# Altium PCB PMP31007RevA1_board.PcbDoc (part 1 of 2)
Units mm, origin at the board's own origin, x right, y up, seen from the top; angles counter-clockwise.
Board outline 45.72 x 49.53 mm, 2 copper layers (Top Layer, Bottom Layer), stack 1.575 mm thick; 68 components, 31 nets, 155 pads, 66 vias.
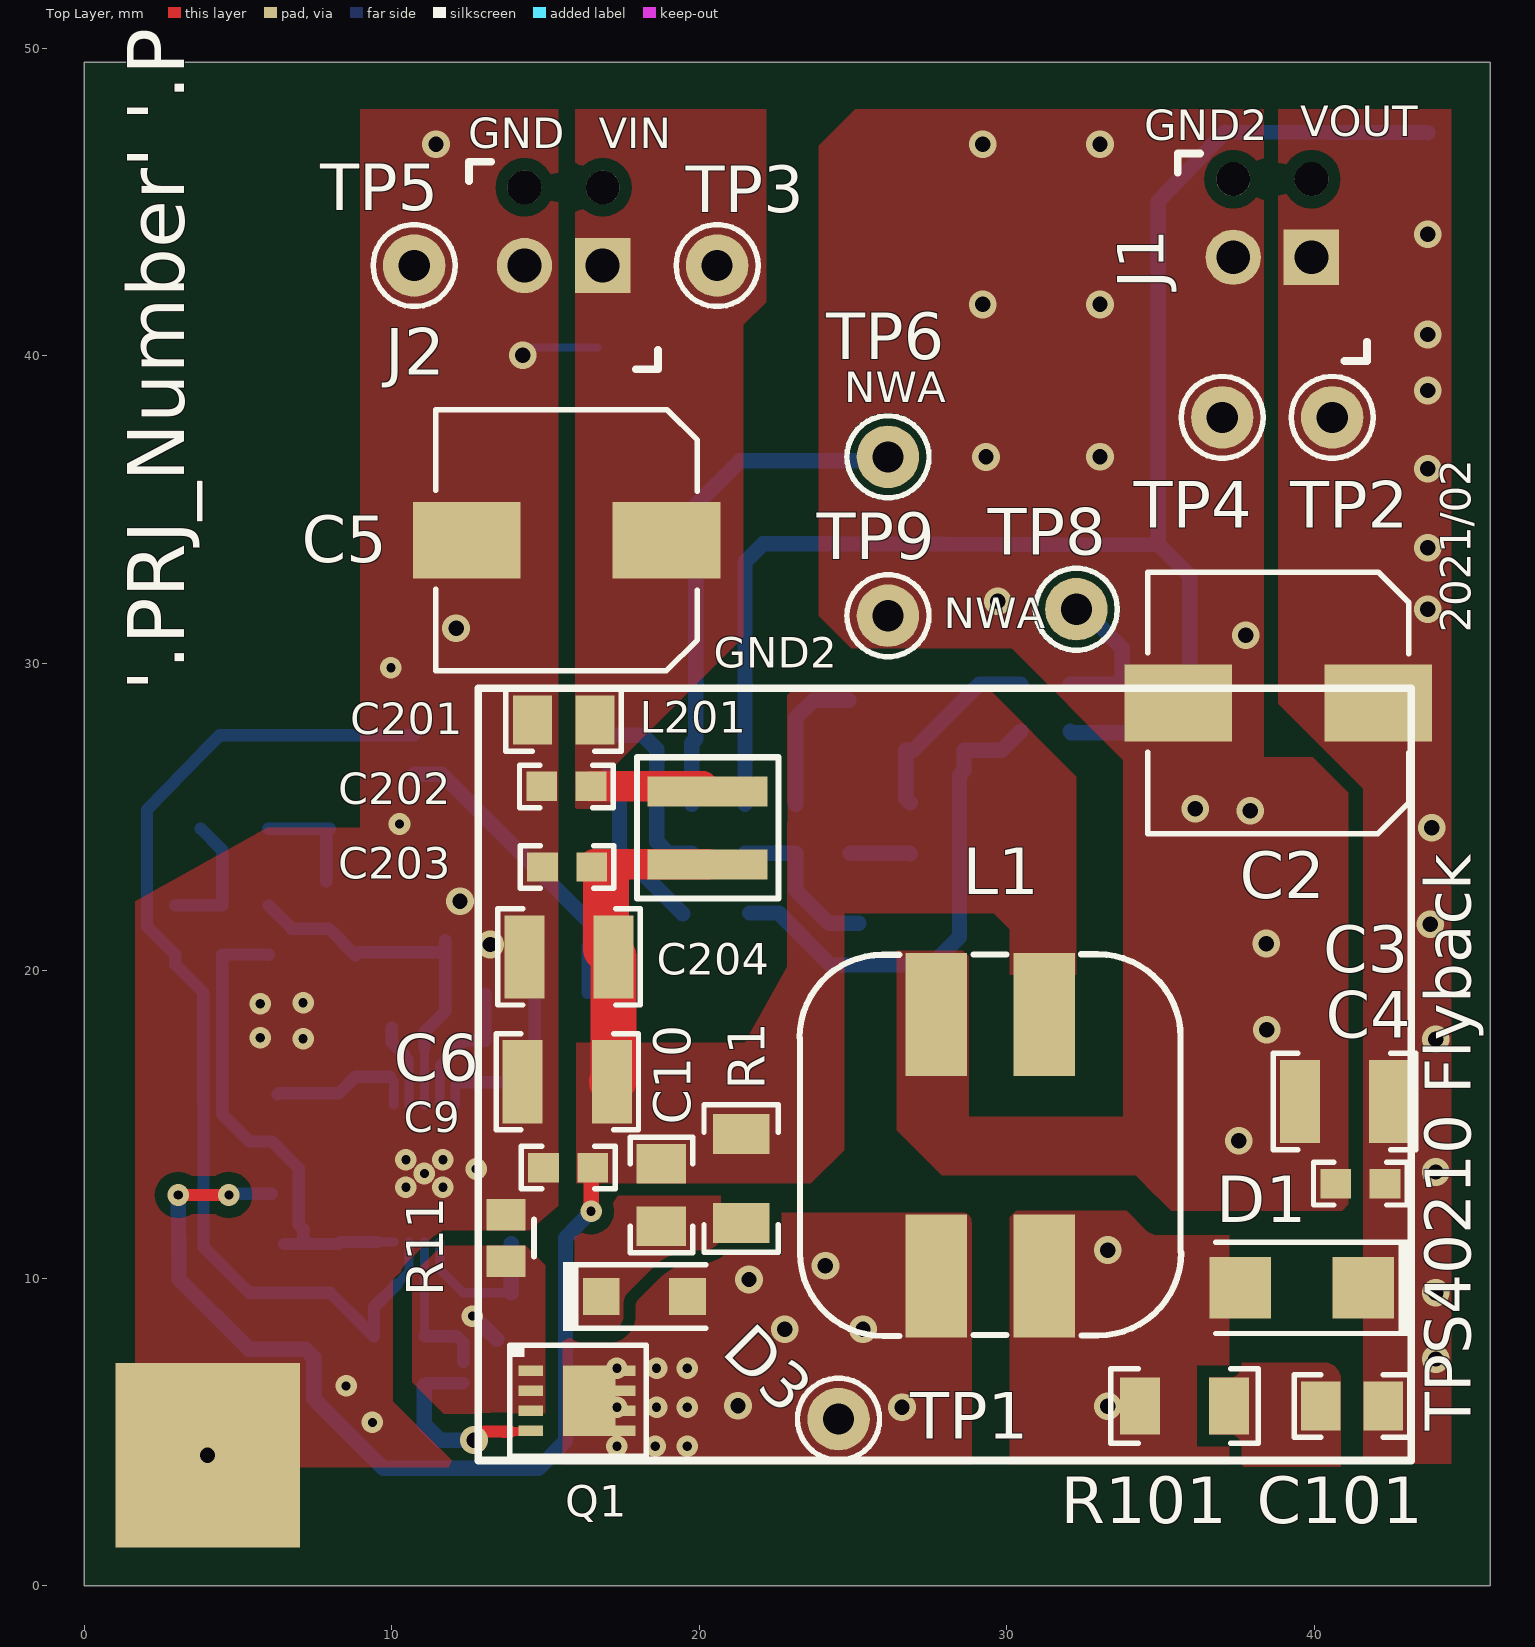
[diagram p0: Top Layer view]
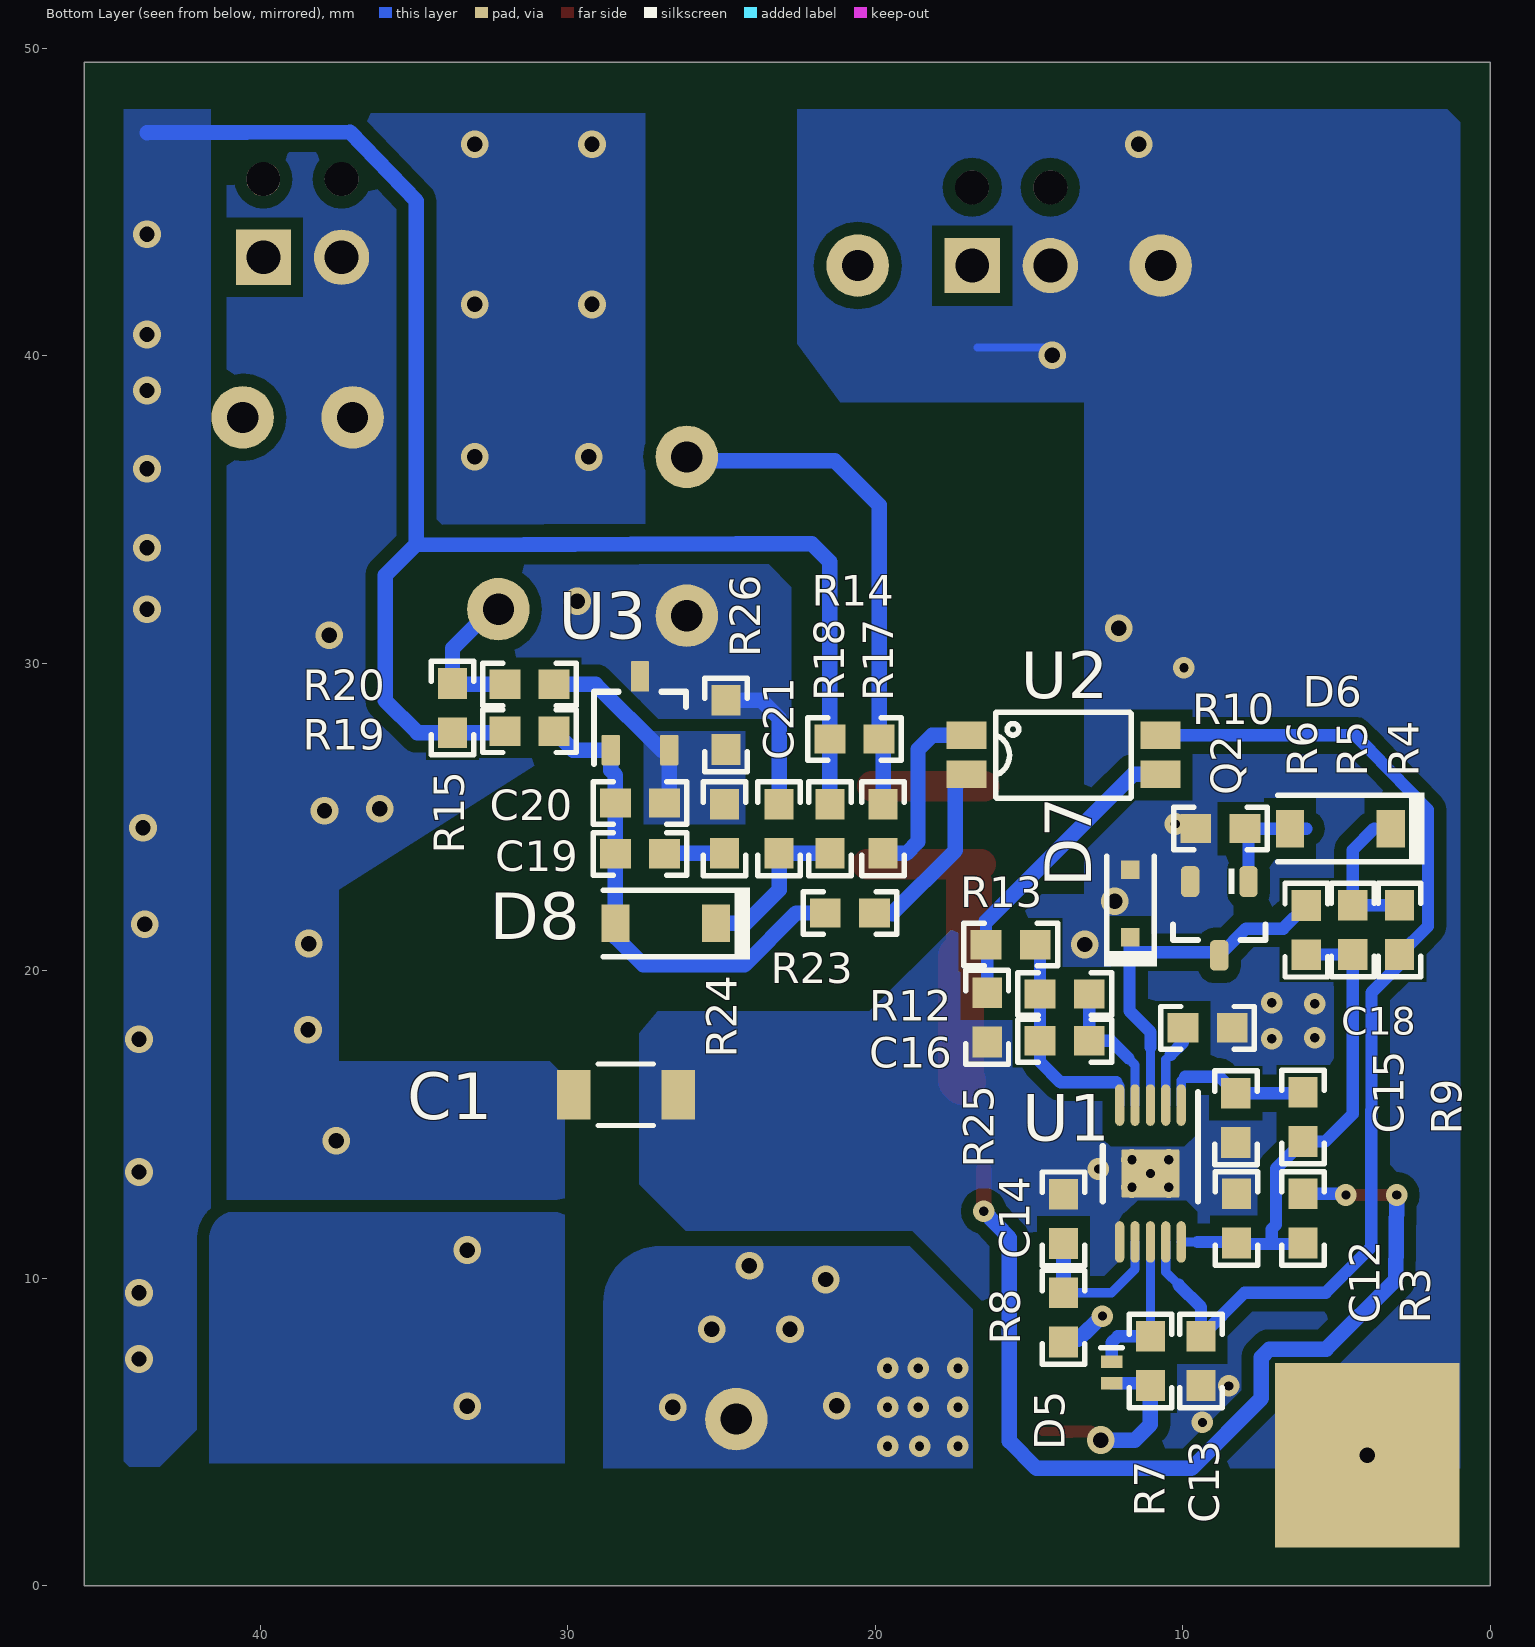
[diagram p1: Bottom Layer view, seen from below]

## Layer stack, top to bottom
Top Solder: solder mask 0.0102, Solder Resist, Dk 3.5
Top Layer: signal copper 0.0356
Dielectric1: core 1.5037, FR-4, Dk 4.8
Bottom Layer: signal copper 0.0356
Bottom Solder: solder mask 0.0102, Solder Resist, Dk 3.5

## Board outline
0,0 0,49.53 45.72,49.53 45.72,0

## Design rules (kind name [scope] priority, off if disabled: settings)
AcuteAngle [All] p1: minimum=4.50000000000000E+0001 checktracksonly=FALSE
AssemblyTestPointUsage [All] p1: valid=2
BoardOutlineClearance BoardOutlineClearance_MountingHoles [OnCopper and InComponentClass('Mounting Holes')] p1: gap=1.016 ignorepadtopadclearanceinfootprint=FALSE
BoardOutlineClearance BoardOutlineClearance_Poly [OnCopper and IsPoly] p2: gap=0.635 ignorepadtopadclearanceinfootprint=FALSE
BoardOutlineClearance [OnCopper and Not InComponentClass('Logo') and not InComponentClass('FiducialMark') and not InRegion(1000,500,4000,800) and not InPoly] p3: gap=1.905 ignorepadtopadclearanceinfootprint=FALSE
Clearance Clearance_Keepouts [((IsTrack Or IsArc) And Not InPoly) And IsFree and IsKeepOut vs ((IsTrack Or IsArc) And Not InPoly) And IsFree and IsKeepOut] p1: gap=0 ignorepadtopadclearanceinfootprint=FALSE
Clearance Clearance_Poly [InPolygon] p2: gap=0.4 ignorepadtopadclearanceinfootprint=FALSE except(0: Arc-Hole Track-Hole SMDPad-Hole THPad-Hole Via-Hole Fill-Hole Poly-Hole Region-Hole Text-Hole)
Clearance Clearance_FiducialMark [IsKeepOut and InComponentClass('FiducialMark') vs IsPad and InComponentClass('FiducialMark')] p3: gap=0 ignorepadtopadclearanceinfootprint=FALSE
Clearance [All] p4: gap=0.2 ignorepadtopadclearanceinfootprint=FALSE except(0: Arc-Hole Track-Hole SMDPad-Hole THPad-Hole Via-Hole Fill-Hole Poly-Hole Region-Hole Text-Hole)
ComponentClearance ComponentClearance_MountingHoles_FiducialMarks [InComponentClass('Mounting Holes') vs InComponentClass('FiducialMark')] p1: gap=1.27 collisioncheckmode=3 verticalgap=0.254 showdistances=FALSE
ComponentClearance ComponentClearance_Shunt [InComponentClass('Header') vs InComponentClass('Shunt')] p2: gap=0 collisioncheckmode=3 verticalgap=0 showdistances=FALSE
ComponentClearance ComponentClearance_Logo [InComponentClass('Logo')] p3: gap=1.27 collisioncheckmode=3 verticalgap=0.254 showdistances=FALSE
ComponentClearance ComponentClearance_ScrewToNut [(HasFootprint('NY PMS 440 0025 PH')) vs (HasFootprint('Keystone_1902C'))] p4: gap=0.127 collisioncheckmode=3 verticalgap=0.254 showdistances=FALSE
ComponentClearance ComponentClearance_MountingHoles [InComponentClass('Mounting Holes')] p5: gap=6.35 collisioncheckmode=3 verticalgap=2540 showdistances=FALSE
ComponentClearance ComponentClearance_SmallPassives [HasFootprint('0201*') or HasFootprint('0402*') or HasFootprint('0508') or HasFootprint('0603*') or HasFootprint('0612') or HasFootprint('0805*') or HasFootprint('0815*') or HasFootprint('0830*') or HasFootprint('1206*') or HasFootprint('1210*') or HasFootprint('1808*') or HasFootprint('1812*') or HasFootprint('1825*') or HasFootprint('2010*') or HasFootprint('2220*') or HasFootprint('2225*') or HasFootprint('2512*') or HasFootprint('2728*') or HasFootprint('3518*') or HasFootprint ('X1-DFN1006-2') vs HasFootprint('0201*') or HasFootprint('0402*') or HasFootprint('0508') or HasFootprint('0603*') or HasFootprint('0612') or HasFootprint('0805*') or HasFootprint('0815*') or HasFootprint('0830*') or HasFootprint('1206*') or HasFootprint('1210*') or HasFootprint('1808*') or HasFootprint('1812*') or HasFootprint('1825*') or HasFootprint('2010*') or HasFootprint('2220*') or HasFootprint('2225*') or HasFootprint('2512*') or HasFootprint('2728*') or HasFootprint('3518*') or HasFootprint ('X1-DFN1006-2')] p6: gap=0.38 collisioncheckmode=3 verticalgap=0.254 showdistances=FALSE
ComponentClearance ComponentClearance_THtoSMT [IsThruComponent vs IsSMTComponent] p7: gap=1.016 collisioncheckmode=3 verticalgap=0.762 showdistances=FALSE
ComponentClearance ComponentClearance_THtoTH [IsThruComponent vs IsThruComponent] p8: gap=0.762 collisioncheckmode=3 verticalgap=0.762 showdistances=FALSE
ComponentClearance [All] p9: gap=0.762 collisioncheckmode=3 verticalgap=0.254 showdistances=FALSE
DiffPairsRouting [All] p1: maxlimit=2.54 minlimit=0.254 mostfreqgap=0.254 toplayer_minwidth=0.381 toplayer_maxwidth=0.381 toplayer_prefwidth=0.381 bottomlayer_minwidth=0.381 bottomlayer_maxwidth=0.381 bottomlayer_prefwidth=0.381 maxuncoupledlength=25.4
FabricationTestPointUsage TestPointUsage [All] p1: valid=2 allowmultiple=FALSE
FabricationTestpoint Testpoint [All] p1: side=3 testpointundercomponent=TRUE minsize=1.016 maxsize=2.54 preferedsize=1.524 minholesize=0 maxholesize=1.016 preferedholesize=0.813 testpointgrid=0.025 allowsidetop=TRUE allowsidebottom=TRUE usegrid=TRUE gridtolerance=0
FanoutControl Fanout_LCC [IsLCC] p1: bgadir=Out bgaviamode=Centered fanoutstyle=Auto fanoutdirection=Alternating viagrid=0.025 // Fanout_LCC (Default Rule)
FanoutControl Fanout_BGA [IsBGA] p2: bgadir=Out bgaviamode=Centered fanoutstyle=Auto fanoutdirection=Alternating viagrid=0.025 // Fanout_BGA (Default Rule)
FanoutControl Fanout_Default [All] p4: bgadir=Out bgaviamode=Centered fanoutstyle=Auto fanoutdirection=Alternating viagrid=0.025 // Fanout_Default (Default Rule)
FanoutControl Fanout_Small [(CompPinCount < 5)] p5: bgadir=Out bgaviamode=Centered fanoutstyle=Auto fanoutdirection=OutThenIn viagrid=0.025 // Fanout_Small (Default Rule)
HoleSize [All] p1: absolutevalues=TRUE maxlimit=6.375 minlimit=0.3 maxpercent=80.000 minpercent=20.000
MinimumAnnularRing MinimumAnnularRing_ThermalPadVias [IsVia and InAnyComponent] p1: minimumring=0.15
MinimumAnnularRing [All] p2: minimumring=0.2
MinimumSolderMaskSliver MinimumSolderMaskSliver_Logo [InComponentClass('Logo') vs InComponentClass('Logo')] p1: minsoldermaskwidth=0.018
MinimumSolderMaskSliver [All] p2: minsoldermaskwidth=0.1
PlaneConnect [All] p1: planeconnectstyle=Relief reliefexpansion=0.254 reliefentries=4 reliefconductorwidth=0.254 reliefairgap=0.254
PolygonConnect [All] p1: connectstyle=Direct reliefconductorwidth=0.254 reliefentries=4 polygonreliefangle="90 Angle" airgapwidth=0.254
RoutingVias ThermalPadVias [IsVia and InAnyComponent] p1: holewidth=0.3 width=0.7 viastyle="Through Hole" minholewidth=0.3 minwidth=0.6 maxholewidth=0.6 maxwidth=1.6
RoutingVias [All] p2: holewidth=0.3 width=0.7 viastyle="Through Hole" minholewidth=0.3 minwidth=0.6 maxholewidth=1.016 maxwidth=2
SilkToBoardRegionClearance [Not ((IsComment or IsDesignator) And (Hide <> 'False')) and not InRegion(1000,500,4000,800)] p1:
SilkToSilkClearance SilkToSilkClearance_Pb-FreeLogo [(HasFootprint('Pb-Free_Overlay_Medium') OR HasFootprint('Pb-Free_Overlay_Small')) vs (HasFootprint('Pb-Free_Overlay_Medium') OR HasFootprint('Pb-Free_Overlay_Small'))] p1: silktosilkclearance=0
SilkToSilkClearance [All] p2: silktosilkclearance=0.102
SilkToSolderMaskClearance SilkToComponentPadClearance [(IsPad or IsFill or IsRegion) and InAnycomponent] p1: minsilkscreentomaskgap=0.127 clearancetoexposedcopper=TRUE
SilkToSolderMaskClearance "Silk to Solder Mask Opening" [All] p2: minsilkscreentomaskgap=0.102 clearancetoexposedcopper=FALSE
SolderMaskExpansion [All] p1: expansion=0.05 istentingtop=FALSE
Width [All] p1: maxlimit=2.54 minlimit=0.152 preferedwidth=0.254 checkconnectedcopper=TRUE
15 further rules are at their usual default settings.

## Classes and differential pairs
net class L201_Nets: NetC6_1 VIN
net class C204_Nets: GND NetC6_1
net class C203_Nets: GND NetC6_1
net class C202_Nets: GND VIN
net class C201_Nets: GND VIN
net class U3_Nets: GND2 NetC19_2 NetC20_2
net class U2_Nets: NetR13_1 NetR17_1 NetR23_2 VBP
net class U1_Nets: GND NetC12_1 NetC14_1 NetC15_1 NetC16_1 NetC16_2 NetC18_1 NetD5_1 NetD7_1 VBP
net class TP9_Nets: GND2
net class TP8_Nets: NetR15_2
net class TP6_Nets: NetR14_1
net class TP5_Nets: GND
net class TP4_Nets: GND2
net class TP3_Nets: VIN
net class TP2_Nets: VOUT
net class TP1_Nets: NetD3_2
net class R101_Nets: NetC101_2 NetD1_2
net class R26_Nets: GND2 NetC20_2
net class R25_Nets: GND NetR13_1
net class R24_Nets: NetC19_1 NetC20_2
net class R23_Nets: NetC19_2 NetR23_2
net class R20_Nets: NetC20_2 NetR15_2
net class R19_Nets: NetC19_2 VOUT
net class R18_Nets: NetC21_1 VOUT
net class R17_Nets: NetR14_1 NetR17_1
net class R15_Nets: NetR15_2 VOUT
net class R14_Nets: NetR14_1 VOUT
net class R13_Nets: NetC16_2 NetR13_1
net class R12_Nets: NetC16_1 NetC16_2
net class R11_Nets: GND NetQ1_1
net class R10_Nets: GND NetD6_2
net class R9_Nets: NetC12_1 NetC15_1
net class R8_Nets: NetC14_1 NetQ1_1
net class R7_Nets: NetD5_1 NetD5_2
net class R6_Nets: NetC12_1 NetD7_1
net class R5_Nets: NetC12_1 NetD6_1
net class R4_Nets: NetD6_1 VBP
net class R3_Nets: NetC6_1 NetC12_1
net class R1_Nets: NetC6_1 NetC10_2
net class Q2_Nets: GND NetD6_2 NetD7_1
net class Q1_Nets: NetD3_2 NetD5_2 NetQ1_1
net class L1_Nets: GND2 NetC6_1 NetD1_2 NetD3_2
net class J2_Nets: GND VIN
net class J1_Nets: GND2 VOUT
net class D8_Nets: NetC19_2 NetC21_1
net class D7_Nets: GND NetD7_1
net class D6_Nets: NetD6_1 NetD6_2
net class D5_Nets: NetD5_1 NetD5_2
net class D3_Nets: NetC10_2 NetD3_2
net class D1_Nets: NetD1_2 VOUT
net class C101_Nets: NetC101_2 VOUT
net class C21_Nets: GND2 NetC21_1
net class C20_Nets: NetC19_2 NetC20_2
net class C19_Nets: NetC19_1 NetC19_2
net class C18_Nets: GND NetC18_1
net class C16_Nets: NetC16_1 NetC16_2
net class C15_Nets: GND NetC15_1
net class C14_Nets: GND NetC14_1
net class C13_Nets: GND VBP
net class C12_Nets: GND NetC12_1
net class C10_Nets: NetC6_1 NetC10_2
net class C9_Nets: GND NetC6_1
net class C6_Nets: GND NetC6_1
net class C5_Nets: GND VIN
net class C4_Nets: GND2 VOUT
net class C3_Nets: GND2 VOUT
net class C2_Nets: GND2 VOUT
net class C1_Nets: GND GND2

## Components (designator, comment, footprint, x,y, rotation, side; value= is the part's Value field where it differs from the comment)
C1 "C1206C102KGRACAUTO" 1206_180 28.111,15.958 r180 bottom value=1000pF
C2 "EEHZA1H680P" SM_RADIAL_8MM 38.821,28.702 r180 top value=68uF
C3 "GRM32ER71H106KA12L" 1210_270 40.975,15.735 r180 top value=10uF
C4 "GCM188R71H104KA57D" 0603 41.491,13.068 r180 top value=0.1uF
C5 "EEHZA1H680P" SM_RADIAL_8MM 15.678,33.992 r180 top value=68uF
C6 "GRM32ER71H106KA12L" 1210_270 15.701,16.383 r180 top value=10uF
C9 "GCM188R71H104KA57D" 0603 15.731,13.589 r180 top value=0.1uF
C10 "GRM21BR72A103MA01L" 0805_HV 18.759,12.7 r270 top value=0.01uF
C12 "UMK107AB7105KA-T" 0603 8.254,11.938 r90 bottom value=1uF
C13 "GRM188R71C105KA12D" 0603 9.413,7.303 r270 bottom value=1uF
C14 "GRM188R71H221KA01D" 0603 13.884,11.924 r90 bottom value=220pF
C15 "GRM1885C1H471JA01D" 0603 8.278,15.21 r270 bottom value=470pF
C16 "GRM1885C1H101JA01D" 0603 13.844,17.717 r0 bottom value=100pF
C18 "GRM188R71C105KA12D" 0603 9.197,18.138 r180 bottom value=1uF
C19 "GRM188R71E332KA01D" 0603 27.654,23.795 r0 bottom value=3300pF
C20 "GRM1885C1H470JA01D" 0603 27.654,25.446 r180 bottom value=47pF
C21 "GRM188R71C105KA12D" 0603 23.13,24.61 r90 bottom value=1uF
C101 "GRM2165C2A221JA01D" 0805_HV 41.22,5.842 r180 top value=220pF
C201 "GRM21BR71H105KA12L" 0805_HV 15.582,28.15 r180 top value=1uF
C202 "885012206114" 0603 15.671,25.991 r180 top value=0.01uF
C203 "GCM188R71H104KA57D" 0603 15.693,23.368 r180 top value=0.1uF
C204 "GRM32ER71H106KA12L" 1210_270 15.759,20.447 r180 top value=10uF
D1 "B1100-13-F" SMA 39.583,9.682 r180 top value=100V
D3 "BAT46WH,115" SOD-123F 18.206,9.398 r0 top value=100V
D5 "BAT54LP-7" X1-DFN1006-2 12.318,6.932 r270 bottom value=30V
D6 "MMSZ5246B-7-F" SOD-123 4.879,24.615 r0 bottom value=16V
D7 "MMSZ5233BS-7-F" SOD-323 11.705,22.184 r90 bottom value=6V
D8 "MMSD914" SOD-123 26.818,21.533 r0 bottom value=100V
J1 "1725656" CONN_1725656 38.629,43.195 r180 top
J2 "1725656" CONN_1725656 15.579,42.926 r180 top
L1 "MSD1260-223ML" MSD1260 29.46,14.323 r90 top value=22uH
L201 "XEL4030-332MEB" XEL4030_310 20.266,24.638 r270 top value=3.3uH
Q1 "BSZ160N10NS3 G" PG-TSDSON-8 16.057,6.01 r0 top value=100V
Q2 "MMBT2222A" SOT-23 8.816,21.694 r270 bottom value=0.3V
R1 "CRCW120610K0JNEA" 1206 21.357,13.238 r90 top value=10k
R3 "CRCW060310R0FKEA" 0603 6.095,11.938 r90 bottom value=10.0
R4 "CRCW0603249KFKEA" 0603 2.952,21.321 r270 bottom value=249k
R5 "CRCW060320K0FKEA" 0603 4.476,21.321 r270 bottom value=20.0k
R6 "CRCW060320K0FKEA" 0603 5.988,21.313 r270 bottom value=20.0k
R7 "CRCW060310R0FKEA" 0603 11.056,7.303 r90 bottom value=10.0
R8 "CRCW06031K00FKEA" 0603 13.884,8.721 r270 bottom value=1.00k
R9 "CRCW0603200KFKEA" 0603 6.095,15.24 r270 bottom value=200k
R10 "CRCW0603100KFKEA" 0603 8.778,24.615 r180 bottom value=100k
R11 "WSLP0805R0300FEB" WSLP0805 13.715,11.303 r270 top value=0.03
R12 "CRCW060320K0FKEA" 0603 13.844,19.241 r180 bottom value=20.0k
R13 "CRCW06034K99FKEA" 0603 15.6,20.841 r180 bottom value=4.99k
R14 "CRCW060349R9FKEA" 0603 20.679,27.531 r0 bottom value=49.9
R15 "CRCW060349R9FKEA" 0603 33.75,28.536 r90 bottom value=49.9
R17 "CRCW06034K99FKEA" 0603 19.748,24.61 r90 bottom value=4.99k
R18 "CRCW060349K9FKEA" 0603 21.479,24.61 r90 bottom value=49.9k
R19 "CRCW060320K0FKEA" 0603 31.248,27.783 r0 bottom value=20.0k
R20 "CRCW060349K9FKEA" 0603 31.248,29.307 r0 bottom value=49.9k
R23 "CRCW06030000Z0EA" 0603 20.828,21.871 r180 bottom value=0
R24 "CRCW0603100KFKEA" 0603 24.902,24.61 r90 bottom value=100k
R25 "CRCW06031K00FKEA" 0603 16.362,18.479 r90 bottom value=1.00k
R26 "CRCW06035K76FKEA" 0603 24.86,27.986 r270 bottom value=5.76k
R101 "CRCW120622R0JNEA" 1206 35.774,5.842 r0 top value=22
TP1 "5002" Keystone5002 24.521,5.412 r0 top
TP2 "5000" Keystone5000 40.577,37.988 r90 top value=Red
TP3 "5000" Keystone5000 20.574,42.926 r90 top value=Red
TP4 "5001" Keystone5001 37,37.988 r90 top value=Black
TP5 "5001" Keystone5001 10.721,42.926 r90 top value=Black
TP6 "5003" Keystone5003 26.13,36.703 r90 top
TP8 "5003" Keystone5003 32.258,31.75 r90 top
TP9 "5001" Keystone5001 26.13,31.54 r90 top value=Black
U1 "TPS40210" DGQ0010D_N 11.056,13.399 r270 bottom
U2 "TCMT1107" SOP-4 13.884,27.013 r180 bottom
U3 "TL431" DBZ0003A_N 27.654,28.367 r90 bottom

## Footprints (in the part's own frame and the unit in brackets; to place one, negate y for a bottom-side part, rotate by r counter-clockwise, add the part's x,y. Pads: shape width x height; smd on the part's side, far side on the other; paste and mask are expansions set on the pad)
0603 [mm] "0603 from SM-752 data"
  rect 1x0.95 smd: 1(-0.8,0) 2(0.8,0)
  silkscreen extent -1.52,-0.69 1.52,0.69, body extent -0.87,-0.47 0.87,0.47, height 1
0805_HV [mil] "0805 with 30mil clearance between pads"
  rect 50x63 smd: 1(-40,0) 2(40,0)
  silkscreen extent -74,-40 74,40, body extent -43,-29 43,29, height 57
1206 [mm] "1206 from SM-752 data"
  rect 1.3x1.85 smd: 1(-1.45,0) 2(1.45,0)
  silkscreen extent -2.4,-1.21 2.4,1.21, body extent -1.7,-0.9 1.7,0.9, height 1.35
1206_180 [mm] "1206_180"
  rect 1.1x1.6 smd: 1(-1.7,0) 2(1.7,0)
  silkscreen extent -0.9,-1 0.9,1, body extent -1.75,-0.95 1.75,0.95, height 1.8
1210_270 [mm] "1210"
  rect 1.3x2.7 smd: 1(-1.45,0) 2(1.45,0)
  silkscreen extent -2.32,-1.57 2.32,1.57, body extent -1.7,-1.35 1.7,1.35, height 2.7
CONN_1725656 [mm] "Phoenix Contact"
  rect 1.8x1.8 hole 1.1: 1(-1.27,0)
  round 1.8 hole 1.1: 2(1.27,0)
  round 1.1 hole 1.1 unplated: MH1(-1.275,-2.54) MH2(1.27,-2.54)
  silkscreen extent -3.08,-3.37 3.08,3.37, body extent -2.77,-3.1 2.77,3.1, height 8.52
DBZ0003A_N [mm] "SOT23, 3-Leads, Body 2.9x1.3mm, Pitch 0.95mm, Lead Span 2.4mm, IPC Medium Density"
  rrect17% 1x0.6 smd: 1(-1.2,0.95) 2(-1.2,-0.95) 3(1.2,0)
  silkscreen extent -1.65,-1.5 0.7,1.5, body extent -1.26,-1.46 1.26,1.46, height 0.98
DGQ0010D_N [mm] "TSSOP, 10-Leads, Body 3x3mm, Pitch 0.5mm, Thermal Pad 1.88x1.57mm, IPC Medium Density"
  rrect100% 1.35x0.3 smd: 1(-2.225,1) 2(-2.225,0.5) 3(-2.225,0) 4(-2.225,-0.5) 5(-2.225,-1) 6(2.225,-1) 7(2.225,-0.5) 8(2.225,0) 9(2.225,0.5) 10(2.225,1)
  rrect6% 1.57x1.88 smd: 11(0,0)
  silkscreen extent -2.65,-1.55 0.9,1.55, body extent -2.46,-1.5 2.46,1.5, height 1.1
Keystone5000 [mil] "For Keystone 500x miniature loop terminals"
  round 80 hole 40: 1(0,0)
  silkscreen extent -52,-52 52,52, body extent -49,-49 49,49, height 182
Keystone5001 [mil] "For Keystone 500x miniature loop terminals"
  round 80 hole 40: 1(0,0)
  silkscreen extent -52,-52 52,52, body extent -49,-49 49,49, height 182
Keystone5002 [mil] "For Keystone 500x miniature loop terminals"
  round 80 hole 40: 1(0,0)
  silkscreen extent -52,-52 52,52, body extent -49,-49 49,49, height 182
Keystone5003 [mil] "For Keystone 500x miniature loop terminals"
  round 80 hole 40: 1(0,0)
  silkscreen extent -52,-52 52,52, body extent -49,-49 49,49, height 182
MSD1260 [mm] "COILCRAFT"
  rect 4x2 smd mask+0.051: 1(-4.25,1.753) 2(-4.25,-1.753) 3(4.25,-1.753) 4(4.25,1.753)
  silkscreen extent -6.21,-6.21 6.21,6.21, body extent -6.1,-6.1 6.1,6.1, height 6
PG-TSDSON-8 [mm] "Infineon recommended land pattern"
  rect 0.8x0.34 smd: 1(-1.538,0.975) 2(-1.538,0.325) 3(-1.538,-0.325) 4(-1.538,-0.975)
  rect 0.65x0.34 smd: 5(1.538,-0.975) 6(1.538,-0.325) 7(1.538,0.325) 8(1.538,0.975)
  rect 1.71x2.29 smd: 9(0.358,0)
  silkscreen extent -2.22,-1.8 2.22,1.8, body extent -1.7,-1.7 1.7,1.7, height 1.1
SM_RADIAL_8MM [mm] "Nichicon 8x10"
  rect 3.5x2.5 smd: 1(-3.25,0) 2(3.25,0)
  silkscreen extent -4.25,-4.25 4.25,4.25, body extent -4.25,-4.25 4.25,4.25, height 10.5
SMA [mm] "Molded Diode, 2-Leads, Body 4.3x2.6mm, IPC Medium Density, based on OnSemi component dimensions and land pattern"
  rect 2x2 smd: 1(-2,0) 2(2,0)
  silkscreen extent -3.66,-1.57 2.79,1.57, body extent -2.6,-1.3 2.6,1.3, height 2.42
SOD-123 [mm] "On Semi recommended land pattern"
  rect 0.915x1.22 smd: 1(-1.637,0) 2(1.637,0)
  silkscreen extent -2.74,-1.17 2.03,1.17, body extent -1.93,-0.9 1.93,0.9, height 1.35
SOD-123F [mm] "NXP recommended land pattern"
  rect 1.2x1.2 smd paste-0.05: 1(-1.4,0) 2(1.4,0)
  silkscreen extent -2.64,-1.12 2.01,1.12, body extent -1.8,-0.85 1.8,0.85, height 1.2
SOD-323 [mm] "NXP recommended land pattern"
  rect 0.6x0.6 smd paste-0.05: 1(-1.1,0) 2(1.1,0)
  silkscreen extent -2.06,-0.86 1.53,0.86, body extent -1.3,-0.67 1.3,0.68, height 1.1
SOP-4 [mm] "Vishay Half Pitch Mini-Flat Package"
  rect 1.3x0.9 smd: 1(-3.15,0.635) 2(-3.15,-0.635) 3(3.15,-0.635) 4(3.15,0.635)
  silkscreen extent -2.2,-1.41 2.2,1.39, body extent -3.5,-1.4 3.5,1.4, height 2.12
SOT-23 [mm] "SOT23, 3-Leads, Body 2.9x1.3mm, Pitch 0.95mm, Lead Span 2.5mm, IPC Medium Density"
  rrect50% 1x0.6 smd: 1(-1.2,0.95) 2(-1.2,-0.95) 3(1.2,0)
  silkscreen extent -1.63,-1.5 0.7,1.5, body extent -1.16,-1.45 1.21,1.45, height 1
WSLP0805 [mm] "Vishay"
  rect 1.02x1.27 smd: 1(-0.76,0) 2(0.76,0)
  silkscreen extent -0.6,-0.9 0.6,0.9, body extent -1.14,-0.76 1.14,0.76, height 0.64
X1-DFN1006-2 [mm] "DIODES, INC"
  rect 0.4x0.7 smd: 1(-0.35,0) 2(0.35,0)
  silkscreen extent -0.8,-0.35 -0.8,0.35, body extent -0.54,-0.34 0.54,0.34, height 0.53
XEL4030_310 [mm] "SMD, 2-Leads, Body 4x4mm, Pitch 2.37mm"
  rect 0.98x3.9 smd: 1(-1.185,0) 2(1.185,0)
  silkscreen extent -2.3,-2.3 2.3,2.3, body extent -2.15,-2.15 2.15,2.15, height 3.1

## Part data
C1: "CAP, CERM, 1000 pF, 2000 V,+/- 10%, X7R, AEC-Q200 Grade 1, 1206", Cap_Case=1206, Manufacturer=Kemet, Supplier Part Number 1=399-12976-1-ND, TempCo=X7R, Tolerance_%=10, Value2=2000V, ValueDisplayed=1000pF
C2 C5: "CAP, Polymer Hybrid, 68 µF, 50 V,+/- 20%, 30 ohm, 8x10 SMD", Manufacturer=Panasonic, Supplier Part Number 1=P15445CT-ND, Tolerance_%=20, Value1="30 ohm", Value2=50V, ValueDisplayed=68µF
C3 C6 C204: "CAP, CERM, 10 µF, 50 V,+/- 10%, X7R, 1210", Cap_Case=1210, Manufacturer=MuRata, Supplier Part Number 1=490-6544-1-ND, TempCo=X7R, Tolerance_%=10, Value1=Unknown, Value2=50V, ValueDisplayed=10µF
C4 C9 C203: "CAP, CERM, 0.1 µF, 50 V, +/- 10%, X7R, 0603", Cap_Case=0603, Manufacturer=MuRata, Supplier Part Number 1=490-4779-1-ND, TempCo=X7R, Tolerance_%=10, Value1="0.02 ohm", Value2=50V, ValueDisplayed=0.1µF
C10: "CAP, CERM, 0.01 µF, 100 V, +/- 20%, X7R, 0805", Cap_Case=0805, Manufacturer=MuRata, Supplier Part Number 1=490-1653-1-ND, TempCo=X7R, Tolerance_%=20, Value1=Unknown, Value2=100V, ValueDisplayed=0.01µF
C12: "CAP, CERM, 1 µF, 50 V,+/- 10%, X7R, 0603", Cap_Case=0603, Manufacturer="Taiyo Yuden", Supplier Part Number 1=587-3247-1-ND, TempCo=X7R, Tolerance_%=10, Value2=50V, ValueDisplayed=1µF
C13 C21: "CAP, CERM, 1 µF, 16 V, +/- 10%, X7R, 0603", Cap_Case=0603, Manufacturer=MuRata, Supplier Part Number 1=490-3900-1-ND, TempCo=X7R, Tolerance_%=10, Value1="0.011 ohm", Value2=16V, ValueDisplayed=1µF
C14: "CAP, CERM, 220 pF, 50 V,+/- 10%, X7R, 0603", Cap_Case=0603, Manufacturer=MuRata, Supplier Part Number 1=490-1483-1-ND, TempCo=X7R, Tolerance_%=10, Value1=Unknown, Value2=50V, ValueDisplayed=220pF
C15: "CAP, CERM, 470 pF, 50 V, +/- 5%, C0G/NP0, 0603", Cap_Case=0603, Manufacturer=MuRata, Supplier Part Number 1=490-1443-1-ND, TempCo=C0G/NP0, Tolerance_%=5, Value1=Unknown, Value2=50V, ValueDisplayed=470pF
C16: "CAP, CERM, 100 pF, 50 V,+/- 5%, C0G/NP0, 0603", Cap_Case=0603, Manufacturer=MuRata, Supplier Part Number 1=490-1427-1-ND, TempCo=C0G/NP0, Tolerance_%=5, Value2=50V, ValueDisplayed=100pF
C18: "CAP, CERM, 1 µF, 16 V,+/- 10%, X7R, 0603", Cap_Case=0603, Manufacturer=MuRata, Supplier Part Number 1=490-3900-1-ND, TempCo=X7R, Tolerance_%=10, Value1="0.011 ohm", Value2=16V, ValueDisplayed=1µF
C19: library part CMP-0007186-4, "CAP, CERM, 1500 pF, 50 V, +/- 5%, C0G/NP0, 0603", Cap_Case=0603, Manufacturer=MuRata, Supplier Part Number 1=GRM188R71E332KA01D-ND, TempCo=X7R, Tolerance_%=10, Value2=25V, ValueDisplayed=15nF
C20: library part CMP-0007196-4, "CAP, CERM, 22 pF, 50 V, +/- 5%, C0G/NP0, 0603", Cap_Case=0603, Manufacturer=MuRata, Supplier Part Number 1=490-1419-1-ND, TempCo=C0G/NP0, Tolerance_%=5, Value2=50V, ValueDisplayed=33pF
C101: library part CMP-0008093-2, "CAP, CERM, 100 pF, 100 V, +/- 5%, C0G/NP0, 0805", Cap_Case=0805, Manufacturer=MuRata, Supplier Part Number 1=490-1607-1-ND, TempCo=C0G/NP0, Tolerance_%=5, Value2=100V, ValueDisplayed=-
C201: "CAP, CERM, 1 µF, 50 V,+/- 10%, X7R, 0805", Cap_Case=0805, Manufacturer=MuRata, Supplier Part Number 1=490-4736-1-ND, TempCo=X7R, Tolerance_%=10, Value2=50V, ValueDisplayed=1µF
C202: library part CMP-0079993-1, "CAP, CERM, 0.01 µF, 100 V,+/- 10%, X7R, 0603", Cap_Case=0603, Manufacturer="Wurth Elektronik", Supplier Part Number 1=45AC8565, TempCo=X7R, Tolerance_%=10%, Value2=100V, ValueDisplayed=0.01µF
D1: library part CMP-0028371-2, "Diode, Schottky, 100 V, 1 A, SMA", Manufacturer="Diodes Inc.", Value1=1A, Value2=0.79V
D3: "Diode, Schottky, 100 V, 0.25 A, SOD-123F", Manufacturer=Nexperia, Supplier Part Number 1=568-6016-1-ND, Value1=0.25A, Value2=0.85V
D5: "Diode, Schottky, 30 V, 0.2 A, 1.00x0.50x0.60mm", Manufacturer="Diodes Inc.", Supplier Part Number 1=BAT54LPDICT-ND, Value1=0.2A, Value2=1V
D6: library part CMP-0005744-4, "Diode, Zener, 14 V, 500 mW, SOD-123", Manufacturer="Diodes Inc.", Power_W=500mW, Value1=0.5W
D7: "Diode, Zener, 6 V, 200 mW, SOD-323", Manufacturer="Diodes Inc.", Power_W=0.2, Supplier Part Number 1=MMSZ5233BS-FDICT-ND, Value1=0.2W
D8: library part MMSD914T1G, "Diode, Switching, 100 V, 0.2 A, SOD-123", Manufacturer="ON Semiconductor", Supplier Part Number 1=MMSD914T1GOSCT-ND, Value1=0.2A, Value2=V
J1 J2: library part CMP-0055479-2, "Terminal Block, 100mil, 2x1, 6A, 63V, TH", Manufacturer="Phoenix Contact", Supplier Part Number 1=71C4107
L1: library part CMP-0012866-2, "Coupled inductor, 22 uH, 6.8 A, 0.096 ohm, TH", Manufacturer=Coilcraft, ValueDisplayed=22µH
L201: "Inductor, Shielded, 3.3 µH, 5 A, 0.0286 ohm, SMD", Manufacturer=Coilcraft, Value1="0.0286 ohm", Value2=5A, ValueDisplayed=3.3µH
Q1: library part CMP-0000952-2, "MOSFET, N-CH, 100 V, 28 A, PG-TSDSON-8", Alternate Manufacturer=None, Manufacturer="Infineon Technologies", Supplier Part Number 1="BSZ160N10NS3 GINCT-ND", Value1=0.02, Value2="19 nC"
Q2: library part "MMBT2222A, Fairchild Semiconductor", "Transistor, NPN, 40V, 0.15A, SOT-23", Manufacturer="Fairchild Semiconductor", Supplier Part Number 1=MMBT2222AFSCT-ND, Value1=0.15A, Value2=300
R1: "RES, 10 k, 5%, 0.25 W, 1206", Manufacturer=Vishay-Dale, Power_W=0.25, Supplier Part Number 1=541-10KECT-ND, TempCo="200 ppm/C", Tolerance_%=5, Value1=5%, Value2=0.25W, Value_Code=10k0, ValueDisplayed=10k
R3 R7: "RES, 10.0, 1%, 0.1 W, 0603", Manufacturer=Vishay-Dale, Power_W=0.1, Supplier Part Number 1=541-10.0HCT-ND, TempCo="100 ppm/C", Tolerance_%=1, Value1=1%, Value2=0.1W, Value_Code=10R0, ValueDisplayed=10.0
R4: library part CMP-0022447-4, "RES, 49.9 k, 1%, 0.1 W, AEC-Q200 Grade 0, 0603", Manufacturer=Vishay-Dale, Power_W=0.1, Supplier Part Number 1=541-249KHCT-ND, TempCo="100 ppm/C", Tolerance_%=1, Value1=1%, Value2=0.1W, Value_Code=249k
R5 R6 R12 R19: "RES, 20.0 k, 1%, 0.1 W, 0603", Manufacturer=Vishay-Dale, Power_W=0.1, Supplier Part Number 1=541-20.0KHCT-ND, TempCo="100 ppm/C", Tolerance_%=1, Value1=1%, Value2=0.1W, Value_Code=20k0, ValueDisplayed=20.0k
R8 R25: "RES, 1.00 k, 1%, 0.1 W, 0603", Manufacturer=Vishay-Dale, Power_W=0.1, Supplier Part Number 1=541-1.00KHCT-ND, TempCo="100 ppm/C", Tolerance_%=1, Value1=1%, Value2=0.1W, Value_Code=1k00, ValueDisplayed=1.00k
R9: library part CMP-0022320-4, "RES, 301 k, 1%, 0.1 W, AEC-Q200 Grade 0, 0603", Manufacturer=Vishay-Dale, Power_W=0.1, Supplier Part Number 1=541-200KHCT-ND, TempCo="100 ppm/C", Tolerance_%=1, Value1=1%, Value2=0.1W, Value_Code=200k, ValueDisplayed=300k
R10: "RES, 100k ohm, 1%, 0.1W, 0603", Manufacturer=Vishay-Dale, Power_W=0.1, Supplier Part Number 1=541-100KHCT-ND, TempCo="100 ppm/C", Tolerance_%=1, Value1=1%, Value2=0.1W, Value_Code=100k
R11: library part CMP-0065348-2, "RES, 0.04, 1%, .125 W, AEC-Q200 Grade 1, 0805", Manufacturer=Vishay-Dale, Power_W=0.5, Supplier Part Number 1=WSLPB-.03CT-ND, TempCo="75 ppm/C", Tolerance_%=1, Value1=1%, Value2=0.5W, Value_Code=R030, ValueDisplayed=0.03
R13: library part CMP-0022379-4, "RES, 3.65 k, 1%, 0.1 W, AEC-Q200 Grade 0, 0603", Manufacturer=Vishay-Dale, Power_W=0.1, Supplier Part Number 1=541-4.99KHCT-ND, TempCo="100 ppm/C", Tolerance_%=1, Value1=1%, Value2=0.1W, Value_Code=4k99, ValueDisplayed=4.99k
R14 R15: "RES, 49.9, 1%, 0.1 W, 0603", Manufacturer=Vishay-Dale, Power_W=0.1, Supplier Part Number 1=541-49.9HCT-ND, TempCo="100 ppm/C", Tolerance_%=1, Value1=1%, Value2=0.1W, Value_Code=49R9, ValueDisplayed=49.9
R17: "RES, 4.99 k, 1%, 0.1 W, 0603", Manufacturer=Vishay-Dale, Power_W=0.1, Supplier Part Number 1=541-4.99KHCT-ND, TempCo="100 ppm/C", Tolerance_%=1, Value1=1%, Value2=0.1W, Value_Code=4k99, ValueDisplayed=4.99k
R18 R20: "RES, 49.9 k, 1%, 0.1 W, 0603", Manufacturer=Vishay-Dale, Power_W=0.1, Supplier Part Number 1=541-49.9KHCT-ND, TempCo="100 ppm/C", Tolerance_%=1, Value1=1%, Value2=0.1W, Value_Code=49k9, ValueDisplayed=49.9k
R23: "RES, 0, 5%, 0.1 W, 0603", Manufacturer=Vishay-Dale, Power_W=0.1, Supplier Part Number 1=541-0.0GCT-ND, TempCo="200 ppm/C", Tolerance_%=5, Value1=5%, Value2=0.1W, Value_Code=0000, ValueDisplayed=0
R24: "RES, 100 k, 1%, 0.1 W, 0603", Manufacturer=Vishay-Dale, Power_W=0.1, Supplier Part Number 1=541-100KHCT-ND, TempCo="100 ppm/C", Tolerance_%=1, Value1=1%, Value2=0.1W, Value_Code=100k
R26: "RES, 5.76 k, 1%, 0.1 W, 0603", Manufacturer=Vishay-Dale, Power_W=0.1, Supplier Part Number 1=541-5.76KHCT-ND, TempCo="100 ppm/C", Tolerance_%=1, Value1=1%, Value2=0.1W, Value_Code=5k76, ValueDisplayed=5.76k
R101: library part CMP-0018575-3, "RES, 100, 5%, 0.25 W, AEC-Q200 Grade 0, 1206", Manufacturer=Vishay-Dale, Power_W=0.25, Supplier Part Number 1=541-22ECT-ND, TempCo="200 ppm/C", Tolerance_%=5, Value1=5%, Value2=0.25W, Value_Code=22R0, ValueDisplayed=-
TP1: "Test Point, Miniature, White, TH", Color=White, Manufacturer=Keystone, Supplier Part Number 1=36-5002-ND
TP2 TP3: "Test Point, Miniature, Red, TH", Manufacturer=Keystone, Supplier Part Number 1=5000K-ND
TP4 TP5 TP9: "Test Point, Miniature, Black, TH", Manufacturer=Keystone, Supplier Part Number 1=5001K-ND
TP6 TP8: "Test Point, Miniature, Orange, TH", Color=Orange, Manufacturer=Keystone, Supplier Part Number 1=36-5003-ND
U1: library part TPS40210QDGQRQ1, "4.5-V TO 52-V INPUT CURRENT MODE BOOST CONTROLLER, DGQ0010D", Alternate Manufacturer="Texas Instruments"
U2: "Optocoupler, 3.75 kV, 80-160% CTR, SMT", Manufacturer=Vishay-Semiconductor, Supplier Part Number 1=TCMT1107CT-ND, Voltage_Isolation_Vrms=3750V
U3: library part TL431AIDBZR, "Adjustable Precision Shunt Regulator, 34 ppm / degC, 100 mA, -40 to 85 degC, 3-pin SOT-23 (DBZ), Green (RoHS & no Sb/Br)", Alternate Manufacturer="Texas Instruments", Alternate PartNumber=Equivalent, Rating=Catalog, Supplier Part Number 1=296-17329-2-ND, Temp Coeff(Max)(ppm/ degree C)=92, Temp Coeff(Typ)(ppm/ degree C)=34

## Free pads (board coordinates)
  rect 6x6 hole 0.5: 1(4.001,4.235)

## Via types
v1: diameter 0.9, hole 0.5, Top Layer to Bottom Layer, tented top, 21 vias
v2: diameter 0.7, hole 0.3, Top Layer to Bottom Layer, 18 vias
v3: diameter 0.9, hole 0.5, Top Layer to Bottom Layer, 17 vias
v4: diameter 0.7, hole 0.3, Top Layer to Bottom Layer, tented bottom, 9 vias
v5: diameter 0.9, hole 0.5, Top Layer to Bottom Layer, tented bottom, 1 vias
